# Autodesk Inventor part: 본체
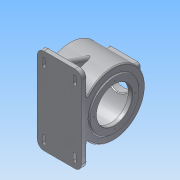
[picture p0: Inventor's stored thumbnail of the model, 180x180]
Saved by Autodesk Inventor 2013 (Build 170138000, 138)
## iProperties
Created: 2015-06
Part Number: 본체
Material: 알루미늄 6061
Document SubType Name: Modeling
Designer: ST
Density: 1 g/cm^3
Author: ST
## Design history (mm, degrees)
sketch "스케치1"
  geometry: L1 (0, 0)-(134, 0); L2 (0, 0)-(0, 65); L3 (0, 65)-(13, 65); L4 (13, 65)-(13, 85); L5 (13, 85)-(131, 85); L6 (131, 85)-(131, 65); L7 (131, 65)-(134, 65); L8 (7.5, 0)-(7.5, 15); L9 (7.5, 15)-(10.5, 15); L10 (10.5, 15)-(10.5, 23.5); L11 (10.5, 23.5)-(24.5, 23.5); L12 (24.5, 23.5)-(24.5, 29.368); L13 (24.5, 29.368)-(21, 31); L14 (21, 31)-(21, 77); L15 (21, 77)-(123, 77); L16 (123, 77)-(123, 47.5); L17 (123, 47.5)-(134, 47.5); L18 (134, 47.5)-(134, 65)
  constraints: 36 end point, 9 parallel, 5 perpendicular, 1 collinear, 1 horizontal, 1 point on line
  dimensions: "d5" = 134 distance of L1.start L1.end; "d7" = 170 diameter of L5 L1; "d8" = 130 diameter of L3 L1; "d9" = 30 diameter of L9 L1; "d10" = 47 diameter of L11 L1; "d11" = 62 diameter of L13.end L1; "d14" = 8 distance between parallel lines of L14 L4; "d16" = 130 diameter of L7 L1; "d17" = 8 distance between parallel lines of L16 L6; "d18" = 102 distance between parallel lines of L14 L16; "d19" = 134 distance between parallel lines of L18 L2; "d20" = 95 diameter of L17 L1; "d21" = 154 diameter of L15 L1; "d23" = 3 distance between parallel lines of L8 L10; "d24" = 115 deg angle of L14 L13; "d25" = 13 distance of L2.end L3.end; "d26" = 3.5 distance between parallel lines of L14 L12; "d27" = 14 distance between parallel lines of L12 L10
revolve "회전1" sketch "스케치1" stored, may be unused: angle "d28" = 90 deg
node "작업 평면1"
sketch "스케치2"
  geometry: L1 (59, 115)-(-59, 115); L2 (-59, 115)-(-59, -115); L3 (-59, -115)-(59, -115); L4 (59, 115)-(59, -115); 1 further point
  constraints: 8 end point, 2 perpendicular, 1 horizontal, 1 parallel
  dimensions: "d29" = 230 distance of L3.end L1.start; "d31" = 115 distance from line of L1 point (72, 0); "d33" = 118 distance of L1.start L1.end; "d34" = 13 distance from line of point (72, 0) L4
extrude "돌출1" join sketch "스케치2" distance "d35" = 14; taper "d36" = 0 deg
sketch "스케치3"
  geometry: L1 (0, 0)-(134.437, 0); L2 (0, -65)-(0, 65) reference; L3 (0, -65)-(0, 65) reference; L4 (0, 65)-(13, 65) reference; L5 (13, 65)-(13, 85) reference; L6 (13, 85)-(131, 85) reference; L7 (131, 85)-(131, 65) reference; L8 (131, 65)-(134, 65) reference; L9 (134, 65)-(134, 47.5) reference; L10 (134, 47.5)-(123, 47.5) reference; L11 (123, 47.5)-(123, 77) reference; L12 (123, 77)-(21, 77) reference; L13 (21, 77)-(21, 31) reference; L14 (21, 31)-(24.5, 29.368) reference; L15 (24.5, 29.368)-(24.5, 23.5) reference; L16 (24.5, 23.5)-(10.5, 23.5) reference; L17 (10.5, 23.5)-(10.5, 15) reference; L18 (10.5, 15)-(7.5, 15) reference; L19 (7.5, 15)-(7.5, -15) reference; L20 (7.5, -15)-(10.5, -15) reference; L21 (10.5, -15)-(10.5, -23.5) reference; L22 (10.5, -23.5)-(24.5, -23.5) reference; L23 (24.5, -23.5)-(24.5, -29.368) reference; L24 (24.5, -29.368)-(21, -31) reference; L25 (21, -31)-(21, -71) reference; L26 (21, -71)-(123, -71) reference; L27 (123, -71)-(123, -47.5) reference; L28 (123, -47.5)-(134, -47.5) reference; L29 (134, -47.5)-(134, -65) reference; L30 (134, -65)-(131, -65) reference; L31 (131, -65)-(131, -85) reference; L32 (131, -85)-(13, -85) reference; L33 (13, -85)-(13, -65) reference; L34 (13, -65)-(0, -65) reference; L35 (123, 47.5)-(21, 47.5); L36 (21, -71)-(21, 77) reference
  constraints: 4 end point, 2 perpendicular, 1 point on line
revolve "회전2" sketch "스케치3" stored, may be unused: angle "d37" = 90 deg
fillet "모깎기1" dims "d38" = 18
sketch "스케치4"
  geometry: L1 (-50, -81)-(-50, -97); L2 (-32, -97)-(-32, -81); A1 r 18 centre (-41, 97) between (-41, 115) and (-59, 97) reference; A2 r 18 centre (41, 97) between (59, 97) and (41, 115) reference; A3 r 18 centre (-41, -97) between (-59, -97) and (-41, -115) reference; A4 r 18 centre (41, -97) between (41, -115) and (59, -97) reference; A5 r 9 centre (-41, -97) between (-50, -97) and (-32, -97); A6 r 9 centre (-41, -81) between (-32, -81) and (-50, -81); 1 further point
  constraints: 4 end point, 4 point on circle, 3 tangent, 2 centre point, 1 coincident, 1 parallel, 1 vertical, 1 vertical alignment
  dimensions: "d41" = 18 distance between parallel lines of L2 L1; "d42" = 16 distance of A5.centre A6.centre
extrude "돌출2" join sketch "스케치4" distance "d43" = 3; taper "d44" = 0 deg
sketch "스케치5"
  geometry: L1 (-50, -81)-(-50, -97) reference; L2 (-32, -97)-(-32, -81) reference; L3 (-37, -81)-(-37, -97); L4 (-45, -97)-(-45, -81); A1 r 9 centre (-41, -97) between (-50, -97) and (-32, -97) reference; A2 r 9 centre (-41, -81) between (-32, -81) and (-50, -81) reference; A3 r 4 centre (-41, -97) between (-45, -97) and (-37, -97); A4 r 4 centre (-41, -81) between (-37, -81) and (-45, -81)
  constraints: 4 end point, 4 point on circle, 2 centre point, 3 other
  dimensions: "d45" = 8 distance between parallel lines of L3 L4
extrude "돌출3" cut sketch "스케치5" stored distance "d47" = 3; taper "d48" = 0 deg
node "작업 평면2"
node "작업 평면3"
sketch "스케치6"
  geometry: L1 (-42.5, 42.5)-(42.5, 42.5); L2 (42.5, 42.5)-(42.5, -42.5); L3 (42.5, -42.5)-(-42.5, -42.5); L4 (-42.5, -42.5)-(-42.5, 42.5); L5 (59, -85)-(59, 85) reference; 4 further points
  constraints: 8 end point, 2 midpoint, 2 parallel, 1 horizontal, 1 horizontal alignment, 1 perpendicular
  dimensions: "d50" = 85 distance of L3.end L1.start; "d52" = 85 distance of L1.start L1.end; "d53" = 16.5 distance between parallel lines of L5 L2
extrude "돌출4" join sketch "스케치6" stored distance "d54" = 3; taper "d55" = 0 deg
sketch "스케치7"
  geometry: L1 (-42.5, -42.5)-(42.5, -42.5) reference; L2 (42.5, -42.5)-(42.5, 42.5) reference; L3 (42.5, 42.5)-(-42.5, 42.5) reference; L4 (-42.5, 42.5)-(-42.5, -42.5) reference; L5 (-42.5, 42.5)-(-42.5, -42.5) reference; L6 (-42.5, 0)-(42.5, 0); C1 r 35 at (0, 0)
  constraints: 3 midpoint, 2 end point, 1 centre point
  dimensions: "d56" = 70 diameter of C1
extrude "돌출5" cut sketch "스케치7" stored distance "d58" = 3; taper "d59" = 0 deg
fillet "모깎기2" dims "d60" = 7
sketch "스케치8"
  geometry: A1 r 7 centre (-35.5, 35.5) between (-35.5, 42.5) and (-42.5, 35.5) reference; A2 r 7 centre (35.5, 35.5) between (42.5, 35.5) and (35.5, 42.5) reference; A3 r 7 centre (35.5, -35.5) between (35.5, -42.5) and (42.5, -35.5) reference; A4 r 7 centre (-35.5, -35.5) between (-42.5, -35.5) and (-35.5, -42.5) reference; 4 further points
  constraints: 4 coincident
hole "구멍1" sketch "스케치8" at (-35.5, 35.5), (35.5, 35.5), (35.5, -35.5), (-35.5, -35.5) diameter "d61" = 3.242; stored, may be unused: countersink angle "d65" = 90 deg, drill point angle "d67" = 118 deg; dims "d62" = 10, "d63" = 4, "d64" = 2, "d66" = 13
sketch "스케치9"
  geometry: L1 (-115, -71)-(-46.733, -71) reference; L2 (-42.5, 73.612)-(-42.5, 88) reference; L3 (-42.5, 88)-(-35, 88) reference; L4 (-35, 88)-(-35, 68.586) reference; L5 (35, 68.586)-(35, 88) reference; L6 (35, 88)-(42.5, 88) reference; L7 (42.5, 88)-(42.5, 73.612) reference; L8 (46.733, -71)-(115, -71) reference; L9 (115, -71)-(115, -85) reference; L10 (115, -85)-(-115, -85) reference; L11 (-115, -85)-(-115, -71) reference; L12 (84.87, -4.703)-(109, -71); L13 (97, -71)-(115, -71) reference; A1 r 85 centre (0, 0) between (-42.5, 73.612) and (-46.733, -71) reference; A2 r 77 centre (0, 0) between (-35, 68.586) and (35, 68.586) reference; A3 r 85 centre (0, 0) between (46.733, -71) and (42.5, 73.612) reference; A4 r 85 centre (0, 0) between (46.733, -71) and (-46.733, -71) reference
  constraints: 2 end point, 2 point on circle, 1 point on line
  dimensions: "d68" = 6 distance from line of L9 L12.end; "d70" = 110 deg angle of L8 L12
extrude "돌출6" join sketch "스케치9" stored distance "d71" = 15; taper "d72" = 0 deg
fillet "모깎기3" dims "d73" = 7.5
node "작업 평면5"
  node "작업 평면4"
sketch "스케치10"
  geometry: L1 (101.5, 23.206)-(101.5, -145.892) reference; 3 further points
  constraints: 1 horizontal alignment, 1 midpoint, 1 other
  dimensions: "d76" = 59 distance of point (101.5, -61.343) point (42.5, -61.343)
feature "엠보싱1" sketch "스케치10" dims "d5" = 134, "d7" = 170, "d8" = 130, "d9" = 30, "d10" = 47, "d11" = 62, "d14" = 8, "d16" = 130, "d17" = 8, "d18" = 102, "d19" = 134, "d20" = 95, "d21" = 154, "d23" = 3, "d24" = 115 deg, "d25" = 13, "d26" = 3.5, "d27" = 14, "d78" = 0.5, "d79" = 0
fillet "모깎기4" dims "d80" = 0.3
chamfer "모따기1" distance "d81" = 1; stored, may be unused: second distance "d82" = 2, angle "d83" = 45 deg
fillet "모깎기5" dims "d84" = 3
fillet "모깎기6" dims "d85" = 3
sketch "스케치11"
  geometry: C1 r 65 at (0, 0) reference; 1 further point
  constraints: 1 vertical alignment
  dimensions: "d86" = 55 distance of C1.centre point (0, 55)
hole "구멍2" sketch "스케치11" at (0, 55) diameter "d87" = 3.242; stored, may be unused: countersink angle "d91" = 90 deg, drill point angle "d93" = 118 deg; dims "d88" = 10, "d89" = 4, "d90" = 2, "d92" = 13
fillet "모깎기7" dims "d97" = 3
chamfer "모따기2" distance "d98" = 1; stored, may be unused: second distance "d99" = 2, angle "d100" = 45 deg
node "솔리드1"
mirror "대칭1"
mirror "대칭2"
mirror "대칭3"
pattern_circular "원형 패턴1" dims angle "d95" = 360 deg
node "투영된 루프1"
node "투영된 루프2"
node "절단 모서리 투영1"
node "절단 모서리 투영2"
other parameters: "d49" = -173, "d74" = -25 deg
